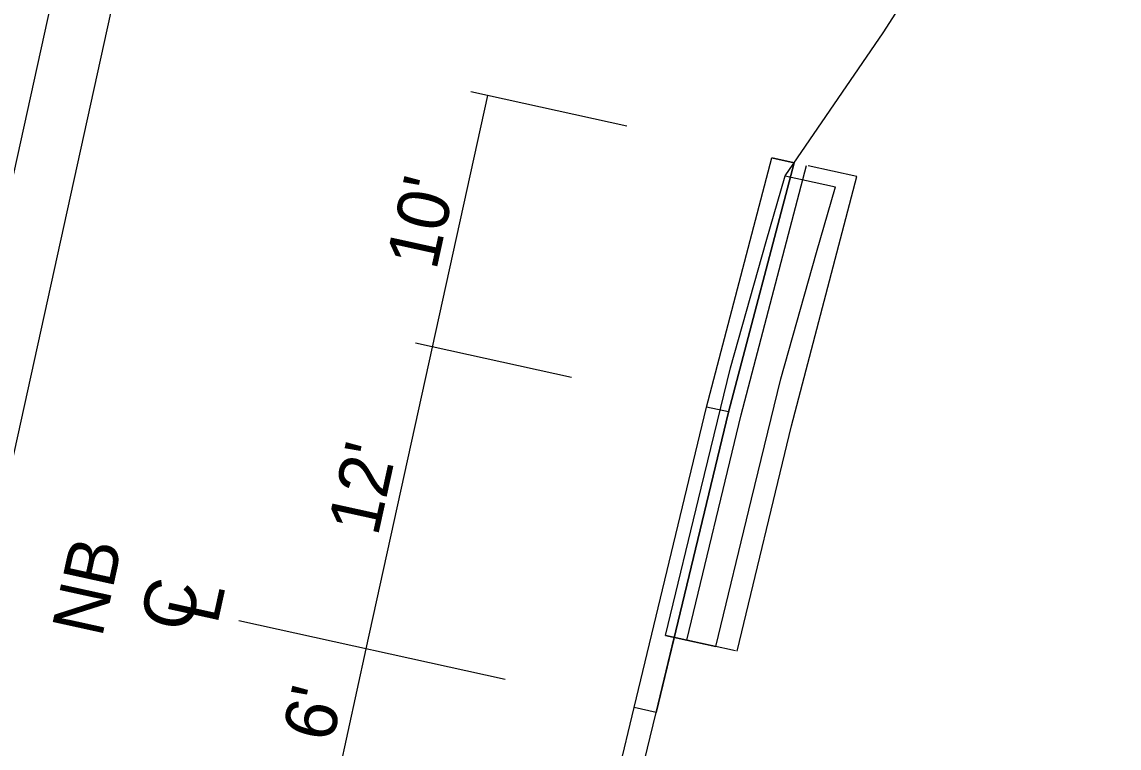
# Model space of a CAD drawing. Extents: x 14104283 to 14128447, y 8633203 to 8671666.
# Drawn here: x 14107425.9 to 14107596.3, y 8639491.6 to 8639604.4 of the extents above; entities that cross this region are included whole.
import ezdxf

# ---------------------------------------------------------------- set-up
doc = ezdxf.new("R2010")
doc.units = 0
for name, color, linetype in [('dsnNonPlotable', 7, 'Continuous'), ('dsnShadingPaved', 7, 'Continuous'), ('dsnTextFinalPlan', 7, 'Continuous'), ('dsnTextOverlapEven', 7, 'Continuous'), ('TC_ShoulderPCC', 7, 'Continuous'), ('TC_Subbase', 7, 'Continuous'), ('TC_SubgradeTreatment', 7, 'Continuous'), ('TC_SubstrataExistingPavement', 7, 'Continuous'), ('Terrain', 7, 'Continuous')]:
    doc.layers.add(name, color=color, linetype=linetype)

msp = doc.modelspace()

# ---------------------------------------------------------------- linework, layer by layer
at = {"layer": 'dsnNonPlotable'}
msp.add_lwpolyline([(14107218.44, 8638642.33), (14107554.83, 8640173.31), (14108541.3, 8639956.56), (14108204.91, 8638425.58)], close=True, dxfattribs=at)
at = {"layer": 'dsnShadingPaved'}
msp.add_lwpolyline([(14107520.99, 8639497.88), (14107532.24, 8639544.57), (14107542.4, 8639583.28), (14107545.82, 8639582.53), (14107535.66, 8639543.8), (14107524.41, 8639497.13)], close=True, dxfattribs=at)
at = {"layer": 'dsnTextFinalPlan'}
for p, q in [((14107519.84, 8639588.23), (14107495.62, 8639593.56)), ((14107489.71, 8639553.9), (14107498.29, 8639592.97)), ((14107511.26, 8639549.17), (14107487.04, 8639554.49)), ((14107479.41, 8639507.02), (14107489.71, 8639553.9)), ((14107500.96, 8639502.28), (14107459.63, 8639511.37)), ((14107474.26, 8639483.58), (14107479.41, 8639507.02))]:
    msp.add_line(p, q, dxfattribs=at)
msp.add_lwpolyline([(14107277.52, 8638867.57), (14107491.18, 8639840), (14107687.99, 8639796.76), (14107474.33, 8638824.33)], close=True, dxfattribs=at)
at = {"layer": 'dsnTextOverlapEven'}
msp.add_lwpolyline([(14107277.52, 8638867.57), (14107491.18, 8639840), (14107687.99, 8639796.76), (14107474.33, 8638824.33)], close=True, dxfattribs=at)
at = {"layer": 'TC_ShoulderPCC'}
for p, q in [((14107532.24, 8639544.57), (14107542.4, 8639583.28)), ((14107545.82, 8639582.53), (14107542.4, 8639583.28)), ((14107535.66, 8639543.8), (14107545.82, 8639582.53)), ((14107520.99, 8639497.88), (14107532.24, 8639544.57)), ((14107524.41, 8639497.13), (14107535.66, 8639543.8)), ((14107535.66, 8639543.82), (14107532.24, 8639544.57)), ((14107524.41, 8639497.13), (14107520.99, 8639497.88))]:
    msp.add_line(p, q, dxfattribs=at)
at = {"layer": 'TC_Subbase'}
for p, q in [((14107537.61, 8639543.38), (14107547.78, 8639582.1)), ((14107529.18, 8639508.37), (14107537.61, 8639543.38)), ((14107524.41, 8639497.13), (14107527.22, 8639508.8)), ((14107529.18, 8639508.37), (14107525.89, 8639509.09))]:
    msp.add_line(p, q, dxfattribs=at)
at = {"layer": 'TC_SubgradeTreatment'}
for p, q in [((14107555.59, 8639580.38), (14107548.01, 8639582.04)), ((14107545.43, 8639541.66), (14107555.59, 8639580.38)), ((14107536.99, 8639506.65), (14107545.43, 8639541.66)), ((14107536.75, 8639506.71), (14107529.18, 8639508.37))]:
    msp.add_line(p, q, dxfattribs=at)
at = {"layer": 'TC_SubstrataExistingPavement'}
for p, q in [((14107544.43, 8639580.51), (14107552.24, 8639578.79)), ((14107525.89, 8639509.09), (14107533.7, 8639507.38)), ((14107513.16, 8639450.46), (14107524.41, 8639497.13))]:
    msp.add_line(p, q, dxfattribs=at)
msp.add_lwpolyline([(14107533.7, 8639507.38), (14107539.21, 8639530.27), (14107543.78, 8639548.94), (14107549.33, 8639568.6), (14107552.24, 8639578.79)], dxfattribs=at)
at = {"layer": 'Terrain'}
msp.add_line((14107509.74, 8639451.2), (14107520.99, 8639497.88), dxfattribs=at)
msp.add_lwpolyline([(14107525.89, 8639509.09), (14107531.4, 8639531.98), (14107535.97, 8639550.66), (14107541.52, 8639570.32), (14107544.43, 8639580.51), (14107559.65, 8639602.7), (14107562.12, 8639606.47), (14107564.43, 8639611.69), (14107571.86, 8639627.66), (14107574.46, 8639635.96), (14107576.29, 8639641.83), (14107585.05, 8639676), (14107585.49, 8639677.86), (14107592.37, 8639692.22), (14107593.58, 8639694.92), (14107592.61, 8639700.55), (14107588.88, 8639719.85), (14107586.35, 8639730.25), (14107583.54, 8639741.75), (14107585.05, 8639748.4), (14107585.92, 8639751.95), (14107585.4, 8639755.02), (14107583.61, 8639766.37), (14107584.86, 8639771.8)], dxfattribs=at)

# ---------------------------------------------------------------- texts
at = {"layer": 'dsnTextFinalPlan'}
for s, p in [("10'", (14107490.26, 8639565.65)), ("12'", (14107481.18, 8639524.32)), ('NB', (14107438.35, 8639508.62)), ('C', (14107452, 8639509.33)), ('L', (14107456.26, 8639510.64)), ("6'", (14107474.14, 8639492.29))]:
    msp.add_text(s, height=8, rotation=77.6078, dxfattribs=at).set_placement(p)

doc.saveas('drawing.dxf')
